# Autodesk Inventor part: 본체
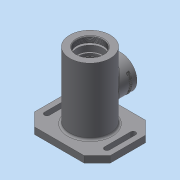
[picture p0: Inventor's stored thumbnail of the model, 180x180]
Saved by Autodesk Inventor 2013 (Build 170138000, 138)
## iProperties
Created: 2017-10
Part Number: 본체
Material: 일반
Document SubType Name: Modeling
Designer: dgall
Density: 1 g/cm^3
Author: dgall
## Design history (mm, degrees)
sketch "스케치1"
  geometry: L1 (-58, 47)-(58, 47); L2 (58, 47)-(58, -47); L3 (58, -47)-(-58, -47); L4 (-58, -47)-(-58, 47); 3 further points
  constraints: 8 end point, 2 midpoint, 2 parallel, 1 horizontal, 1 horizontal alignment, 1 perpendicular, 1 vertical alignment
  dimensions: "d0" = 116 distance of L1.start L1.end; "d2" = 94 distance of L1.end L2.end
extrude "돌출1" new body sketch "스케치1" distance "d3" = 10; taper "d4" = 0 deg
sketch "스케치2"
  geometry: C1 r 31 at (0, 0); 1 further point
  constraints: 1 centre point, 1 coincident
  dimensions: "d5" = 62 diameter of C1
extrude "돌출2" join sketch "스케치2" distance "d7" = 102; taper "d8" = 0 deg
chamfer "모따기1" distance "d9" = 20; stored, may be unused: second distance "d10" = 2, angle "d11" = 45 deg
sketch "스케치3"
  geometry: L1 (-42, -20)-(-42, 20); L2 (-50, -20)-(-50, 20); L3 (50, -20)-(50, 20); L4 (42, -20)-(42, 20); A1 r 4 centre (-46, 20) between (-42, 20) and (-50, 20); A2 r 4 centre (-46, -20) between (-42, -20) and (-50, -20); A3 r 4 centre (46, 20) between (50, 20) and (42, 20); A4 r 4 centre (46, -20) between (50, -20) and (42, -20); 3 further points
  constraints: 8 end point, 8 point on circle, 8 tangent, 4 centre point, 2 equal radius, 2 horizontal alignment, 2 midpoint, 2 vertical alignment
  dimensions: "d12" = 40 distance of A2.centre A1.centre; "d14" = 40 distance of A4.centre A3.centre; "d15" = 8 diameter of A3; "d16" = 8 diameter of A1; "d17" = 46 horizontal distance of A2.centre point (0, 0); "d18" = 46 horizontal distance of point (0, 0) A4.centre
extrude "돌출3" cut sketch "스케치3" distance "d19" = 102; taper "d20" = 0 deg
fillet "모깎기1" dims "d21" = 3
sketch "스케치4"
  geometry: C1 r 35 at (0, 0); 1 further point
  constraints: 1 centre point, 1 coincident
  dimensions: "d22" = 70 diameter of C1
extrude "돌출4" join sketch "스케치4" distance "d24" = 3; taper "d25" = 0 deg
sketch "스케치5"
  geometry: C1 r 31 at (0, 0) reference; 1 further point
  constraints: 1 coincident
hole "구멍1" sketch "스케치5" at (0, 0) diameter "d26" = 40.376; stored, may be unused: countersink angle "d30" = 90 deg, drill point angle "d32" = 0 deg; dims "d27" = 6, "d28" = 4, "d29" = 2, "d31" = 9
node "작업 평면1"
sketch "스케치6"
  geometry: L1 (31, 112)-(-31, 112) reference; L2 (-35, -3)-(35, -3) reference; L3 (0, -3)-(0, 112); L4 (20.188, 103)-(-20.188, 103) reference; L5 (20.188, 103)-(20.188, 112) reference; L6 (20.188, 103)-(24, 103); L7 (24, 103)-(24, 100); L8 (24, 100)-(20, 100); L9 (20, 100)-(20, 91); L10 (20, 91)-(17.5, 91); L11 (17.5, 91)-(17.5, 87.75); L12 (17.5, 87.75)-(18.5, 87.75); L13 (18.5, 87.75)-(18.5, 86); L14 (18.5, 86)-(17.5, 86); L15 (17.5, 86)-(17.5, 75); L16 (17.5, 75)-(26, 75); L17 (26, 75)-(26, 37); L18 (26, 37)-(17.5, 37); L19 (17.5, 37)-(17.5, 26); L20 (17.5, 26)-(16.5, 26); L21 (16.5, 26)-(16.5, 21); L22 (16.5, 21)-(10, 21); L23 (10, 21)-(10, 18.3); L24 (10, 18.3)-(12.5, 18.3); L25 (12.5, 18.3)-(12.5, 11); L26 (12.5, 11)-(16, 11); L27 (16, 11)-(22, -3); 1 further point
  constraints: 46 end point, 19 parallel, 2 midpoint, 2 perpendicular, 1 point on line
  dimensions: "d34" = 3 distance of L6.end L7.end; "d36" = 9 distance of L8.end L9.end; "d37" = 1.75 distance of L12.end L13.end; "d38" = 48 diameter of L7 L3; "d39" = 40 diameter of L9 L3; "d40" = 35 diameter of L11 L3; "d41" = 37 diameter of L13 L3; "d42" = 35 diameter of L15 L3; "d43" = 52 diameter of L17 L3; "d44" = 38 distance of L16.end L17.end; "d45" = 26 vertical distance of L1.start L13.end; "d46" = 11 distance of L14.end L15.end; "d47" = 35 diameter of L19 L3; "d48" = 33 diameter of L21 L3; "d49" = 11 distance of L18.end L19.end; "d50" = 2.7 distance of L22.end L23.end; "d51" = 7.3 distance of L24.end L25.end; "d52" = 14 distance from line of L2 L26.end; "d53" = 44 diameter of L27.end L3; "d54" = 32 diameter of L26.end L3; "d55" = 20 diameter of L23 L3; "d56" = 25 diameter of L25 L3
revolve "회전1" sketch "스케치6" stored, may be unused: angle "d57" = 90 deg
fillet "모깎기2" dims "d58" = 3
fillet "모깎기3" dims "d59" = 3
fillet "모깎기4" dims "d63" = 3
chamfer "모따기3" distance "d64" = 1; stored, may be unused: second distance "d65" = 2, angle "d66" = 30 deg
node "작업 평면2"
sketch "스케치7"
  geometry: L1 (38, 0)-(-38, 0) reference; L2 (31, 112)-(-31, 112) reference; C1 r 25 at (0, 56); 2 further points
  constraints: 1 centre point, 1 midpoint, 1 vertical alignment
  dimensions: "d68" = 56 distance from line of L2 C1.centre; "d69" = 50 diameter of C1
extrude "돌출5" join sketch "스케치7" stored distance "d70" = 3; taper "d71" = 0 deg
fillet "모깎기5" dims "d72" = 3
sketch "스케치8"
  geometry: C1 r 25 at (0, 0) reference; C2 r 16 at (0, 0); 1 further point
  constraints: 1 centre point, 1 coincident
  dimensions: "d73" = 32 diameter of C2
extrude "돌출6" cut sketch "스케치8" stored distance "d75" = 3; taper "d76" = 0 deg
chamfer "모따기4" distance "d88" = 1; stored, may be unused: second distance "d89" = 2, angle "d90" = 30 deg
node "작업 평면3"
sketch "스케치10"
  geometry: L1 (-7.598, 16.346)-(-7.598, -16.346); L2 (-7.598, -16.346)-(-12.402, -16.346); L3 (-12.402, -16.346)-(-12.402, 16.346); L4 (-12.402, 16.346)-(-7.598, 16.346); L5 (-16, 56)-(-78, 56) reference; L6 (0, 25)-(0, -25) reference; 3 further points
  constraints: 2 midpoint, 2 other
  dimensions: "d91" = 56 distance from line of L5 point (-7.598, 0); "d92" = 10 distance from line of L6 point (-10, -16.346)
feature "엠보싱1" sketch "스케치10" dims "d0" = 116, "d2" = 94, "d93" = 0.5, "d94" = 0
sketch "스케치11"
  geometry: C1 r 25 at (0, 0) reference; 2 further points
  constraints: 1 horizontal alignment
  dimensions: "d95" = 20.5 distance of C1.centre point (-20.5, 0)
hole "구멍3" sketch "스케치11" at (-20.5, 0) diameter "d96" = 2.459; stored, may be unused: countersink angle "d100" = 90 deg, drill point angle "d102" = 118 deg; dims "d97" = 6, "d98" = 4, "d99" = 2, "d101" = 8
chamfer "모따기5" distance "d106" = 0.7; stored, may be unused: second distance "d107" = 2, angle "d108" = 30 deg
fillet "모깎기6" dims "d109" = 0.3
node "솔리드1"
pattern_circular "원형 패턴2" dims angle "d104" = 360 deg
other parameters: "d33" = 0, "d67" = 47
